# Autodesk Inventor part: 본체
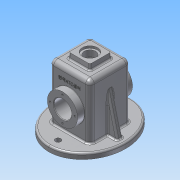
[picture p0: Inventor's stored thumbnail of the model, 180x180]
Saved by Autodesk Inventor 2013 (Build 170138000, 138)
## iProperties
Created: 2017-07
Part Number: 본체
Material: 알루미늄 6061
Document SubType Name: Modeling
Designer: Administrator
Density: 2.71 g/cm^3
Mass: 892.711 g
Surface Area: 987.353 cm^2
Volume: 329.414 cm^3
Author: Administrator
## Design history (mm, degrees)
sketch "스케치1"
  geometry: 4 further points; 1 other entity
  constraints: 1 coincident, 1 horizontal alignment, 1 vertical alignment, 4 other
  dimensions: "d1" = 65 distance of point (0, 0) point (0, 65); "d3" = 75 distance of point (75, 0) point (0, 0)
extrude "돌출1" new body sketch "스케치1" distance "d4" = 10; taper "d5" = 0 deg
sketch "스케치2"
  geometry: L1 (-37, -37)-(37, -37); L2 (37, -37)-(37, 37); L3 (37, 37)-(-37, 37); L4 (-37, 37)-(-37, -37); L5 (-37, -37)-(37, 37); L6 (37, -37)-(-37, 37); 1 further point; 1 other entity
  constraints: 12 end point, 2 midpoint, 2 parallel, 2 perpendicular, 1 horizontal, 1 other
  dimensions: "d6" = 74 distance of L2.end L3.end
extrude "돌출2" join sketch "스케치2" distance "d8" = 100; taper "d9" = 0 deg
sketch "스케치3"
  geometry: L1 (-20, 20)-(20, 20); L2 (20, 20)-(20, -20); L3 (20, -20)-(-20, -20); L4 (-20, -20)-(-20, 20); L5 (-20, 20)-(20, -20); L6 (20, 20)-(-20, -20); 1 further point
  constraints: 12 end point, 2 midpoint, 2 parallel, 2 perpendicular, 1 horizontal
  dimensions: "d10" = 40 distance of L1.start L1.end
extrude "돌출3" join sketch "스케치3" distance "d12" = 10; taper "d13" = -5 deg
sketch "스케치5"
  geometry: L1 (-32, 32)-(32, 32); L2 (32, 32)-(32, -32); L3 (32, -32)-(-32, -32); L4 (-32, -32)-(-32, 32); L5 (-32, 32)-(32, -32); L6 (32, 32)-(-32, -32); 1 further point; 1 other entity
  constraints: 12 end point, 2 midpoint, 2 parallel, 2 perpendicular, 1 horizontal, 1 other
  dimensions: "d20" = 64 distance of L1.start L1.end
extrude "돌출4" cut sketch "스케치5" distance "d22" = 105; taper "d23" = 0 deg
sketch "스케치6"
  geometry: L1 (-71.984, 55)-(71.132, 55); L2 (-75, 0)-(75, 0) reference; L3 (-50, 71)-(-25, 71); L4 (-25, 71)-(-25, 75.5); L5 (-25, 75.5)-(-32, 82.5); L6 (-32, 82.5)-(-50, 82.5); L7 (-50, 82.5)-(-50, 71); L8 (-32, 0)-(-32, 105) reference; L9 (-37, 10)-(-37, 110) reference; 1 further point
  constraints: 12 end point, 2 parallel, 1 horizontal, 1 perpendicular, 1 point on line, 1 vertical
  dimensions: "d24" = 55 distance between parallel lines of L2 L1; "d25" = 32 diameter of L3 L1; "d26" = 55 diameter of L6 L1; "d27" = 135 deg angle of L8 L5; "d28" = 7 distance from line of L8 L4.end; "d29" = 13 distance between parallel lines of L9 L7
revolve "회전1" sketch "스케치6" stored, may be unused: angle "d30" = 90 deg
sketch "스케치7"
  geometry: C1 r 16 at (0, 0) reference; 1 further point
extrude "돌출5" cut sketch "스케치7" distance "d31" = 25; taper "d32" = 0 deg
sketch "스케치8"
  geometry: C1 r 14 at (0, 0); 1 further point
  constraints: 1 centre point, 1 coincident
  dimensions: "d33" = 28 diameter of C1
extrude "돌출6" cut sketch "스케치8" distance "d35" = 4; taper "d36" = 0 deg
sketch "스케치9"
  geometry: C1 r 14 at (0, 0) reference; C2 r 10.5 at (0, 0)
  constraints: 1 centre point, 1 coincident
  dimensions: "d37" = 21 diameter of C2
extrude "돌출7" cut sketch "스케치9" stored distance "d39" = 4; taper "d40" = 0 deg
sketch "스케치10"
  geometry: L1 (-37, 10)-(-37, 110) reference; L2 (65, 10)-(-65, 10) reference; L3 (-37, 82.194)-(-55, 10); L4 (-65, 10)-(-65, -10.331); 1 further point
  constraints: 4 end point, 2 point on line, 1 perpendicular
  dimensions: "d41" = 10 distance of L3.end L2.end; "d42" = 14 deg angle of L3 L4; "d43" = 20.33099 distance of L2.end L4.end
feature "리브1" sketch "스케치10" dims "d44" = 1, "d45" = 10, "d46" = 0, "d47" = 0, "d48" = 1, "d49" = 1
fillet "모깎기1" dims "d50" = 3
sketch "스케치11"
  geometry: 1 further point
sketch "스케치12" dims "d51" = 45
  geometry: C1 r 27.5 at (0, 0) reference; C2 r 16 at (0, 0) reference; 3 further points
  constraints: 2 horizontal alignment, 1 coincident, 2 other
hole "구멍1" sketch "스케치12" at (-22.5, 0) diameter "d53" = 3.242; stored, may be unused: countersink angle "d57" = 90 deg, drill point angle "d59" = 118 deg; dims "d54" = 8, "d55" = 4, "d56" = 2, "d58" = 10
sketch "스케치13"
  geometry: C1 r 5 at (-58, 0); C2 r 5 at (58, 0); 1 further point; 1 other entity
  constraints: 2 centre point, 2 horizontal alignment, 1 equal radius, 1 other
  dimensions: "d63" = 58 distance of C1.centre point (0, 0); "d64" = 116 distance of C2.centre C1.centre; "d65" = 10 diameter of C1
extrude "돌출8" cut sketch "스케치13" stored distance "d66" = 4; taper "d67" = 0 deg
fillet "모깎기2" dims "d68" = 8
fillet "모깎기3" dims "d69" = 3
fillet "모깎기4" dims "d70" = 3
sketch "스케치14"
  geometry: L1 (-18, 48.125)-(-18, 9.875) reference; C1 r 27.5 at (47, 29) reference; 2 further points
  constraints: 1 horizontal alignment, 1 other
  dimensions: "d71" = 30 distance from line of point (12, 29) L1
feature "엠보싱1" sketch "스케치14" dims "d1" = 65, "d3" = 75, "d13" = -5 deg, "d72" = 0.5, "d73" = 0
fillet "모깎기5" dims "d74" = 0.5
fillet "모깎기6" dims "d75" = 0.5
chamfer "모따기1" distance "d76" = 1; stored, may be unused: second distance "d77" = 2, angle "d78" = 45 deg
fillet "모깎기7" dims "d79" = 3
fillet "모깎기8" dims "d80" = 3
sketch "스케치15" dims "d81" = 45
  geometry: C1 r 27.5 at (0, 0) reference; C2 r 17 at (0, 0) reference; 3 further points
  constraints: 2 horizontal alignment, 1 coincident, 2 other
hole "구멍2" sketch "스케치15" at (22.5, 0) diameter "d83" = 3.242; stored, may be unused: countersink angle "d87" = 90 deg, drill point angle "d89" = 118 deg; dims "d84" = 8, "d85" = 4, "d86" = 2, "d88" = 10
node "솔리드1"
mirror "대칭1"
mirror "대칭2"
pattern_circular "원형 패턴1" dims angle "d61" = 360 deg
pattern_circular "원형 패턴2" dims angle "d91" = 360 deg
